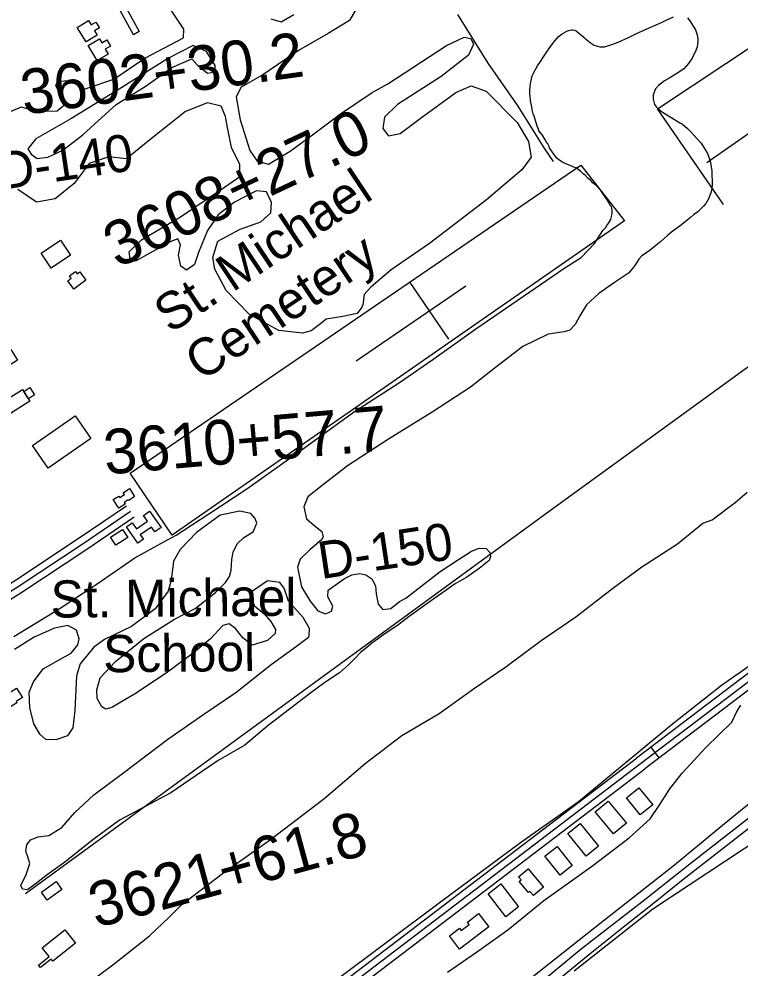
# Model space of a CAD drawing. Extents: x 3419139 to 3457078, y 540382 to 565875.
# Drawn here: x 3441162 to 3442772, y 548472 to 550592 of the extents above; entities that cross this region are included whole.
import ezdxf

# ---------------------------------------------------------------- set-up
doc = ezdxf.new("R2010")
doc.units = 0
for name, color, linetype in [('V-BLDG-IDEN', 7, 'Continuous'), ('V-BLDG-OTLN', 7, 'Continuous'), ('V-DTCH-CNTR', 7, 'Continuous'), ('V-RIVR-RANG-IDEN', 7, 'Continuous'), ('V-ROAD-CNTR', 7, 'Continuous'), ('V-SITE-OTLN', 7, 'Continuous'), ('V-SITE-OTLN-IDEN', 7, 'Continuous'), ('V-SITE-VEGE', 7, 'Continuous'), ('V-SURV-IDEN', 7, 'Continuous'), ('V-TOPO-SHOR', 7, 'Continuous')]:
    doc.layers.add(name, color=color, linetype=linetype)

msp = doc.modelspace()

# ---------------------------------------------------------------- linework, layer by layer
at = {"layer": 'V-BLDG-OTLN'}
for points in [[(3441393.1, 550631.6), (3441430.2, 550564.1), (3441417.2, 550556.9), (3441380.2, 550624.4)], [(3441312.2, 550540.8), (3441291.9, 550572.8), (3441317, 550588.6), (3441323.2, 550578.7), (3441333.3, 550585.1), (3441341.5, 550572), (3441330.7, 550565.2), (3441336.4, 550556.1)], [(3441336.6, 550499.1), (3441316.6, 550532.7), (3441341.4, 550547.5), (3441346.7, 550538.4), (3441358, 550545.1), (3441366, 550531.6), (3441354.1, 550524.5), (3441360.7, 550513.4)], [(3441254.4, 550098.4), (3441277.1, 550064.8), (3441233.9, 550035.7), (3441211.2, 550069.4)], [(3441311.3, 550008.9), (3441284.1, 549989.3), (3441270.7, 550007.8), (3441278.6, 550013.5), (3441274.9, 550018.6), (3441288.1, 550028.1), (3441291.7, 550023.2), (3441297.8, 550027.7)], [(3441185.7, 549738.9), (3441109.7, 549690.7), (3441085.1, 549729.7), (3441076.4, 549724.2), (3441060.2, 549749.6), (3441067.2, 549754), (3441043.7, 549791.1), (3441143.4, 549854.3), (3441158.5, 549830.4), (3441085.9, 549784.3), (3441118.6, 549732.7), (3441169.3, 549764.9)], [(3441185.8, 549769.5), (3441196.6, 549753.2), (3441183.1, 549744.1), (3441172.4, 549760.7)], [(3441322.6, 549655.6), (3441227.1, 549589.6), (3441192.1, 549640.2), (3441287.5, 549706)], [(3441408.5, 549543.7), (3441419.9, 549526.1), (3441406.8, 549517.5), (3441406, 549518.7), (3441396.5, 549512.5), (3441398.6, 549509.3), (3441384.8, 549500.3), (3441372.5, 549519.2), (3441384.8, 549527.3), (3441386.8, 549524.2), (3441397.1, 549530.8), (3441394.6, 549534.6)], [(3441453.5, 549493.4), (3441479, 549456.7), (3441465.5, 549447.4), (3441458, 549458.1), (3441432.8, 549440.6), (3441439.8, 549430.6), (3441427.4, 549422), (3441401.9, 549458.7), (3441414.7, 549467.6), (3441424.4, 549453.7), (3441449.1, 549470.8), (3441439.9, 549484)], [(3441404.6, 549434.5), (3441378.2, 549417.3), (3441366.5, 549435.2), (3441392.9, 549452.4)], [(3441122, 549076.8), (3441156.1, 549098.7), (3441169.6, 549077.6), (3441155.3, 549068.4), (3441157.1, 549065.7), (3441134.9, 549051.5), (3441122.9, 549070.3), (3441125.2, 549071.8)], [(3442549.3, 548815.4), (3442518.4, 548853.7), (3442546.1, 548876.1), (3442577, 548837.8)], [(3442489.2, 548772.9), (3442448.7, 548822.5), (3442477.9, 548846.3), (3442518.4, 548796.7)], [(3442428.8, 548723.4), (3442387.7, 548773.9), (3442415, 548796.2), (3442456.1, 548745.6)], [(3442370.1, 548681.1), (3442336.5, 548723.6), (3442363.4, 548744.9), (3442397.1, 548702.4)], [(3442298.8, 548695.3), (3442333.1, 548654.4), (3442310.5, 548635.5), (3442302.9, 548644.6), (3442299.9, 548642.1), (3442278.9, 548667.1), (3442283, 548670.6), (3442277.4, 548677.3)], [(3441257.6, 548649.2), (3441224.8, 548625.5), (3441212.2, 548643), (3441245, 548666.7)], [(3442249, 548588), (3442209.5, 548639.4), (3442238.1, 548661.4), (3442277.6, 548610)], [(3442210.8, 548566), (3442145.9, 548516), (3442123.2, 548545.5), (3442145.5, 548562.6), (3442149.3, 548557.6), (3442166.9, 548571.2), (3442163.3, 548575.9), (3442188.3, 548595.1)], [(3441288.3, 548529), (3441237.5, 548488.9), (3441233.6, 548493.8), (3441209.6, 548474.8), (3441205.3, 548480.3), (3441229.5, 548499.4), (3441213.9, 548519.1), (3441264.5, 548559.1)]]:
    msp.add_lwpolyline(points, close=True, dxfattribs=at)
at = {"layer": 'V-DTCH-CNTR'}
msp.add_lwpolyline([(3442141.4, 550601.8), (3442209, 550493.2), (3442276, 550397.3), (3442335.4, 550302.1), (3442354.4, 550273.9)], dxfattribs=at)
at = {"layer": 'V-ROAD-CNTR'}
msp.add_line((3442591.8, 548943), (3442573.6, 548966.9), dxfattribs=at)
for points in [[(3446783.6, 552186.4), (3446429.8, 551917.4), (3445909.7, 551525.7), (3445571.6, 551260.5), (3444950.1, 550786.4), (3444277, 550265.9), (3443810, 549903.5), (3443342.9, 549551.1), (3442540.9, 548942.1)], [(3442550, 548930.1), (3443352, 549539.1), (3443819.1, 549891.6), (3444286.2, 550254), (3444959.2, 550774.5), (3445580.8, 551248.6), (3445918.8, 551513.8), (3446438.8, 551905.4), (3446792.6, 552174.4)], [(3446801.7, 552162.5), (3446447.9, 551893.5), (3445928, 551502), (3445590, 551236.8), (3444968.3, 550762.6), (3444295.4, 550242.1), (3443828.2, 549879.7), (3443361, 549527.1), (3442559.1, 548918.2)], [(3441668.5, 547914.2), (3441772.2, 547996.7), (3441914, 548111.6), (3442044.3, 548215.4), (3442175.5, 548318.9), (3442292.2, 548412.8), (3442417.4, 548516.3), (3442555.8, 548623.7), (3442663.7, 548709.1), (3442788.6, 548806.9), (3442888.6, 548885.4), (3443031.6, 548992.2), (3443167.3, 549099.3), (3443278.3, 549183.2), (3443370.8, 549264.2), (3443455.1, 549334.3), (3443569.1, 549423.6), (3443685.2, 549512.4), (3443795.2, 549598.4), (3443909.2, 549686.9), (3444027.1, 549779.2), (3444132.9, 549864.1), (3444245, 549952.8), (3444348.5, 550027.2)], [(3440895.5, 549196), (3440937.8, 549215), (3440990, 549237.1), (3441040.8, 549267.2), (3441152, 549338.2), (3441296.5, 549433.6), (3441402.1, 549505.5)], [(3440901.6, 549182.3), (3440943.8, 549201.2), (3440996.8, 549223.7), (3441048.7, 549254.5), (3441160.1, 549325.6), (3441304.9, 549421.2), (3441410.6, 549493.1)], [(3440907.7, 549168.6), (3440949.8, 549187.5), (3441003.6, 549210.3), (3441056.5, 549241.7), (3441168.3, 549313), (3441313.2, 549408.7), (3441419, 549480.7)], [(3441562.5, 548197), (3442540.9, 548942.1)], [(3441571.6, 548185.1), (3442550, 548930.1)], [(3441580.6, 548173.1), (3442559.1, 548918.2)]]:
    msp.add_lwpolyline(points, dxfattribs=at)
at = {"layer": 'V-SITE-OTLN'}
for p, q in [((3441914.8, 549829.2), (3442159.9, 549996.2)), ((3442121.4, 549877.2), (3442035.1, 550003.8))]:
    msp.add_line(p, q, dxfattribs=at)
msp.add_lwpolyline([(3441409.8, 549578.6), (3442416.8, 550265.7), (3442513.9, 550141.5), (3441503.9, 549439.6)], close=True, dxfattribs=at)
at = {"layer": 'V-SITE-VEGE'}
for p, q in [((3442771.3, 549521.4), (3442788.1, 549535.7)), ((3442743.7, 549500.4), (3442760.5, 549512.4)), ((3442760.5, 549512.4), (3442771.3, 549521.4)), ((3442710.1, 549474.1), (3442721.7, 549482.7)), ((3442721.7, 549482.7), (3442731, 549489.5)), ((3442731, 549489.5), (3442743.7, 549500.4)), ((3442632.5, 549420.8), (3442689.3, 549466.6)), ((3442689.3, 549466.6), (3442710.1, 549474.1)), ((3442552.7, 549369.1), (3442632.5, 549420.8)), ((3442488, 549321.6), (3442552.7, 549369.1)), ((3442405.1, 549257.8), (3442488, 549321.6)), ((3442327.8, 549204.9), (3442405.1, 549257.8)), ((3442249.2, 549145.9), (3442327.8, 549204.9)), ((3442177.2, 549097.2), (3442249.2, 549145.9)), ((3442799.8, 549153), (3442730.7, 549104.3)), ((3442730.7, 549104.3), (3442621.3, 549018.3)), ((3442100.5, 549041.8), (3442177.2, 549097.2)), ((3442764.6, 549046.3), (3442773.9, 549060.5)), ((3442016.5, 548993.1), (3442100.5, 549041.8)), ((3442754.1, 549022.8), (3442764.6, 549046.3)), ((3442621.3, 549018.3), (3442410.2, 548843.7)), ((3442696, 548965.6), (3442754.1, 549022.8)), ((3441934.8, 548929.9), (3442016.5, 548993.1)), ((3442642.7, 548909), (3442696, 548965.6)), ((3441842.9, 548851.7), (3441934.8, 548929.9)), ((3442615.5, 548874), (3442642.7, 548909)), ((3442857.4, 548893.3), (3442737.2, 548795.3)), ((3442593.1, 548838.5), (3442615.5, 548874)), ((3441723.2, 548760.8), (3441842.9, 548851.7)), ((3442410.2, 548843.7), (3442282.1, 548753.5)), ((3442571.3, 548807.1), (3442593.1, 548838.5)), ((3442524.1, 548764.4), (3442571.3, 548807.1)), ((3442577.5, 548606.2), (3442879.7, 548805.9)), ((3442737.2, 548795.3), (3442625.4, 548703.2)), ((3441616.2, 548685), (3441723.2, 548760.8)), ((3442440.1, 548700.6), (3442524.1, 548764.4)), ((3442282.1, 548753.5), (3442100.1, 548618.7)), ((3442333.7, 548624.2), (3442440.1, 548700.6)), ((3442625.4, 548703.2), (3442448.8, 548564.2)), ((3441525.5, 548615.2), (3441616.2, 548685)), ((3441497.1, 548587.6), (3441525.5, 548615.2)), ((3442100.1, 548618.7), (3441866.1, 548443.6)), ((3442253.2, 548559.2), (3442333.7, 548624.2)), ((3442401.5, 548467.7), (3442577.5, 548606.2)), ((3441453.5, 548545.4), (3441497.1, 548587.6)), ((3442183.7, 548509.3), (3442253.2, 548559.2)), ((3442448.8, 548564.2), (3442287.4, 548436.6)), ((3441371.3, 548481), (3441453.5, 548545.4)), ((3442118.4, 548464.8), (3442183.7, 548509.3)), ((3441268.5, 548405.2), (3441371.3, 548481))]:
    msp.add_line(p, q, dxfattribs=at)
for points in [[(3441121, 550376.5), (3441167.8, 550395.8), (3441198.1, 550386), (3441247.3, 550387.1), (3441264.4, 550401), (3441254.1, 550424.1), (3441243.8, 550443), (3441248.1, 550453.3), (3441277.9, 550454.4), (3441307.6, 550435.5), (3441373.8, 550457.9), (3441443.2, 550504.5), (3441529.5, 550549.8), (3441529.6, 550569.2), (3441496.9, 550618.5), (3441453.3, 550676.3), (3441421.2, 550734.1), (3441398.9, 550777.9), (3441395.9, 550808.8)], [(3441916.5, 550616.9), (3441900.1, 550588.4), (3441852.6, 550559.4), (3441785.7, 550521.3), (3441706.7, 550467.4), (3441658, 550439.6), (3441647, 550418.3), (3441656, 550366.7), (3441677.7, 550298.6), (3441693.5, 550274.9), (3441719, 550268.2), (3441767.6, 550297.2), (3441820.5, 550336), (3441879.5, 550380.2), (3441950.7, 550428), (3441985.4, 550447.3)], [(3441724.6, 550592.5), (3441747.6, 550585.7), (3441775.6, 550602.1)], [(3442323, 550342.4), (3442321.7, 550346.4), (3442319.1, 550352.5), (3442317.3, 550358.2), (3442312.6, 550374.8), (3442310.4, 550380.4), (3442308.2, 550389.2), (3442306.9, 550395.7), (3442305.2, 550405.3), (3442303.9, 550410.6), (3442303.5, 550419.7), (3442302.6, 550425.4), (3442302.7, 550431.5), (3442303.6, 550442.8), (3442304.5, 550451.6), (3442307.5, 550465.1), (3442311.5, 550472.9), (3442319.4, 550487.3), (3442326.4, 550496.9), (3442332.9, 550507.3), (3442344.8, 550525.2), (3442353.5, 550536.5), (3442365.8, 550551.8), (3442374.5, 550558.7), (3442385, 550564.8), (3442389.4, 550566.5), (3442395.5, 550567.8), (3442398.5, 550567.8), (3442402.9, 550566.9), (3442405.9, 550565.2), (3442411.6, 550560.8), (3442415.1, 550557.8), (3442423.4, 550551.2), (3442426.4, 550548.1), (3442437.3, 550539.4), (3442446, 550533.7), (3442459.1, 550530.2), (3442469.1, 550530.1), (3442486.1, 550534.9), (3442499.7, 550540.5), (3442523.3, 550551), (3442539.4, 550558.8), (3442562.6, 550569.2), (3442596.6, 550583.9), (3442608.4, 550590), (3442623.3, 550597)], [(3442654.7, 550594.3), (3442660.3, 550587.7), (3442667.7, 550575.9), (3442672.5, 550567.6), (3442675.5, 550558.5), (3442676.8, 550553.7), (3442677.7, 550545.4), (3442677.7, 550540.1), (3442676.3, 550529.7), (3442673.3, 550521.4), (3442664.9, 550504.8), (3442657.1, 550492.6), (3442646.6, 550480.9)], [(3441985.4, 550447.3), (3442116.8, 550532.6), (3442155.7, 550551.4), (3442170.9, 550548.3), (3442176.9, 550535.5), (3442165.9, 550511.3), (3442104.5, 550463.4), (3442007.1, 550401.1), (3441977.9, 550372.6), (3441974.2, 550347.7), (3441986.9, 550331.3), (3442013.1, 550336.7), (3442057.5, 550370), (3442137.2, 550428.1), (3442171.8, 550442.6), (3442205.2, 550431), (3442274.3, 550361), (3442299.7, 550318.4), (3442305.7, 550283.8), (3442285, 550255.3), (3442205.8, 550188.7), (3442078.7, 550091.2), (3441992.9, 550031.9), (3441947.9, 549993.1), (3441932.7, 549976.8), (3441929.6, 549954.3), (3441927.7, 549948.8), (3441916.8, 549934.9), (3441885.2, 549928.3), (3441847.5, 549922.3), (3441835.3, 549911.4), (3441814, 549896.3), (3441794.6, 549890.8), (3441741.8, 549896.4), (3441676.3, 549932.4), (3441624.8, 549986), (3441599.4, 550033.4), (3441594.6, 550059.5), (3441606.2, 550095.9), (3441655.5, 550122.6), (3441701.6, 550139.5), (3441724.2, 550159.4), (3441725.4, 550182.5), (3441714.6, 550206.2), (3441692.1, 550208.1), (3441642.8, 550183.3), (3441606.9, 550154.9), (3441582.6, 550119.7), (3441563, 550070.5), (3441553.8, 550043.8), (3441536.2, 550031.7), (3441522.9, 550040.3), (3441518.1, 550064.6), (3441522.4, 550087.6), (3441516.9, 550101), (3441501.1, 550095.6), (3441453.7, 550069.6), (3441422.1, 550051.4), (3441409.9, 550056.9), (3441408.2, 550072.1), (3441435.5, 550098.8), (3441522.5, 550150.2), (3441621.1, 550216.8), (3441655.1, 550240.4), (3441655.2, 550267.1), (3441636.4, 550305.4), (3441627.4, 550349.8), (3441623.2, 550374.7), (3441613.6, 550397.2), (3441582.6, 550404.5), (3441534, 550385.8), (3441450.6, 550319.2), (3441402, 550279.8), (3441362.5, 550284.2), (3441318.7, 550269.7), (3441285.2, 550224.8), (3441242.6, 550190.3), (3441201.3, 550183.1), (3441158.9, 550211.2)], [(3442646.6, 550480.9), (3442634.8, 550472.2), (3442615.5, 550460.4), (3442603.3, 550453.9), (3442589.8, 550443.9), (3442583.6, 550436.1), (3442577.9, 550422.6), (3442577.9, 550413), (3442581.4, 550401.2), (3442585.3, 550395.1), (3442594.4, 550387.2), (3442602.3, 550381.5), (3442616.2, 550373.6), (3442639.3, 550359.2), (3442643.2, 550357), (3442655, 550347.3), (3442663.2, 550339.5), (3442676.3, 550324.2), (3442685, 550314.6), (3442691.5, 550304.9), (3442698.5, 550293.6), (3442701.5, 550285.7), (3442705.4, 550274.8), (3442707.1, 550266.5), (3442708.9, 550253.4), (3442709.3, 550244.3), (3442710.1, 550229.4), (3442710.1, 550219.8), (3442707.4, 550206.3), (3442704.4, 550198), (3442701.3, 550190.6), (3442695.6, 550180.2), (3442690.8, 550174.5), (3442683.3, 550166.7), (3442677.7, 550161.9), (3442668, 550154.5), (3442661.1, 550148.8), (3442650.1, 550139.7), (3442641.4, 550132.7), (3442628.3, 550123.2), (3442619.1, 550116.2), (3442609.9, 550108.8), (3442595.1, 550095.3), (3442583.7, 550086.2), (3442571.4, 550076.2), (3442551.8, 550062.7), (3442545.8, 550056), (3442538.6, 550044), (3442531.8, 550035.2), (3442523.2, 550024.6), (3442491.4, 550003.9), (3442457, 549979.2), (3442429.5, 549953.7), (3442414.6, 549929.2), (3442403.7, 549910), (3442391.9, 549897.6), (3442379.5, 549893.4), (3442343.6, 549888.7), (3442287.1, 549860.8), (3442226.1, 549814.4), (3442170.1, 549770.2), (3442084.6, 549714.3), (3441986.7, 549653.9), (3441895.2, 549594.3), (3441838.6, 549551), (3441807.2, 549525.1), (3441797.8, 549503.4), (3441803.8, 549476.6), (3441823.9, 549459.3), (3441838.4, 549448.4), (3441841.1, 549436.3), (3441837.4, 549429.4), (3441812.3, 549407.7), (3441789.7, 549386.1), (3441783.9, 549368.6), (3441792.8, 549324.8), (3441812.4, 549292.5), (3441828.9, 549271.3), (3441846.4, 549264.3), (3441860, 549270.3), (3441862.4, 549281.5), (3441851.6, 549302), (3441852.3, 549316.8), (3441889.1, 549343.3), (3441904.8, 549351.1), (3441922.7, 549354.4), (3441936.5, 549351.6), (3441949.8, 549342.5), (3441957.9, 549326.5), (3441959.7, 549308.7), (3441964.1, 549286.1), (3441974.4, 549274.3), (3441992.2, 549276.4), (3442011.5, 549292), (3442026, 549299.2), (3442102.5, 549358.5), (3442143.6, 549385.2), (3442172, 549404.2), (3442189.5, 549410.5), (3442204.9, 549410.1), (3442213.3, 549401.4)], [(3441150.2, 549213.8), (3441251.7, 549275.4), (3441334.2, 549330.1), (3441420.6, 549389.3), (3441485.6, 549424.8), (3441512.8, 549439.8), (3441583.8, 549486.1), (3441670.5, 549543.6), (3441791.7, 549629.3), (3441911.1, 549715.6), (3442009.6, 549779), (3442085.8, 549832.3), (3442182.2, 549900.2), (3442288.6, 549973), (3442381.1, 550036.4), (3442417.6, 550059.3), (3442446.9, 550091.2), (3442466, 550119.6), (3442471.7, 550125.7), (3442474.7, 550131.4), (3442478.7, 550137), (3442483.5, 550144.4), (3442485.2, 550150.6), (3442486.6, 550159.7), (3442486.6, 550165.4), (3442484.9, 550172.8), (3442482.2, 550175.9), (3442478.8, 550182.4), (3442475.3, 550188.1), (3442461.4, 550209.1), (3442450.5, 550220.4), (3442443.5, 550226.6), (3442437.9, 550232.2), (3442433.1, 550236.2), (3442426.1, 550243.2), (3442421.8, 550246.2), (3442416.5, 550251.9), (3442406.1, 550259.4), (3442400.9, 550261.1), (3442393, 550265.1), (3442383, 550269), (3442378.6, 550271.2), (3442373.8, 550273.4), (3442370.8, 550275.6), (3442367.3, 550277.8), (3442363, 550281.7), (3442354.7, 550292.6), (3442349.9, 550299.6), (3442346.9, 550304.4), (3442345.6, 550307.5), (3442344.3, 550310.1), (3442342.5, 550313.2), (3442340.8, 550314.9), (3442339.5, 550316.7), (3442336.4, 550324.1), (3442330.8, 550332.4), (3442323, 550342.4)], [(3442213.3, 549401.4), (3442214.8, 549392.6), (3442211.5, 549383.6), (3442189.7, 549365.2), (3442161.9, 549346), (3442136.2, 549331.2), (3442082.7, 549294), (3442033.2, 549258.5), (3442007.2, 549238.3), (3441979.1, 549219.4), (3441964.6, 549209.4), (3441949.8, 549198.9), (3441938.3, 549189.3), (3441924.7, 549177.9), (3441913.2, 549165.8), (3441898, 549150.2), (3441877.5, 549132.7), (3441844.5, 549111.1), (3441810.4, 549085.5), (3441766, 549051.2), (3441718.5, 549015.4), (3441666.2, 548971.2), (3441606.7, 548936.6), (3441557.7, 548903.5), (3441500.6, 548864.4), (3441386.1, 548803.4), (3441327.1, 548759.8), (3441264.3, 548710.2), (3441224.4, 548681.9), (3441198.1, 548660.6), (3441180.5, 548647.9), (3441169.4, 548649.8), (3441165.8, 548657.9), (3441177.9, 548682.3), (3441186.4, 548706.8), (3441181.6, 548722.2), (3441177.1, 548734.8), (3441179, 548749), (3441187.4, 548759.6), (3441204.4, 548766.8), (3441228.2, 548769.7), (3441257.2, 548787.2), (3441286.3, 548821.2), (3441328.6, 548860.3), (3441396.3, 548910.2), (3441494.5, 548984.8), (3441574.3, 549040.5), (3441645.9, 549088.9), (3441725.1, 549151.5), (3441781.4, 549192.4), (3441808, 549212.5), (3441809.5, 549215.5), (3441810.7, 549231.2), (3441796.6, 549256.3), (3441763.5, 549292.6), (3441753.9, 549321.3), (3441744.3, 549334), (3441716.5, 549338.3), (3441683.3, 549314.8), (3441679.9, 549301.2), (3441687.7, 549282.2), (3441709.4, 549264.1), (3441724.5, 549247.4), (3441734.4, 549229), (3441733.8, 549220.5), (3441716.8, 549204.9), (3441682.7, 549194.4), (3441661.9, 549211.1), (3441645.7, 549231.9), (3441631.5, 549242.2), (3441616.7, 549238), (3441589.2, 549208.2), (3441547.5, 549174.5), (3441493.7, 549134.2), (3441423.6, 549087), (3441369.5, 549055.1), (3441355.6, 549051.2), (3441346.5, 549056.7), (3441336.3, 549075.1), (3441335.5, 549094.4), (3441342.8, 549121.6), (3441377, 549158), (3441440.7, 549209.2), (3441509, 549252.1), (3441555.3, 549275.9), (3441600.6, 549311.7), (3441623.3, 549334.6), (3441632.1, 549347.8), (3441635.7, 549362), (3441637.3, 549385.5), (3441640.3, 549401.8), (3441649.1, 549420.8), (3441664, 549434.9), (3441685.1, 549447.6), (3441693.3, 549466.3), (3441689.1, 549477.4), (3441679.5, 549488.6), (3441655.3, 549493.2), (3441611.3, 549484.6), (3441558.4, 549446.1), (3441521.8, 549407.8)], [(3441521.8, 549407.8), (3441507.2, 549381.9), (3441501.7, 549339.1), (3441494.7, 549315.2), (3441465.9, 549275.5), (3441413.3, 549235.8), (3441352.6, 549206.7), (3441328.8, 549189.8), (3441298.5, 549152.5), (3441290.6, 549126.2), (3441286.5, 549048.4), (3441281.9, 549010.1), (3441270.1, 548992), (3441243.8, 548982.7), (3441222.1, 548983.7), (3441208.8, 548994.9), (3441195.3, 549019), (3441186.3, 549055.3), (3441184.9, 549089.7), (3441194.6, 549112.6), (3441216.1, 549141.2), (3441249.9, 549161), (3441278, 549176.7), (3441293.5, 549195.3), (3441296.5, 549208.3), (3441290.2, 549227.6), (3441270.6, 549238.2), (3441241.3, 549232), (3441195.7, 549212.1), (3441151.9, 549184.5)]]:
    msp.add_lwpolyline(points, dxfattribs=at)
msp.add_lwpolyline([(3441188.8, 550290.1), (3441202.1, 550280.3), (3441226.4, 550283.9), (3441259.9, 550299), (3441304.3, 550333.5), (3441338.4, 550365), (3441379.2, 550400.8), (3441446.1, 550442.5), (3441503.2, 550483.7), (3441547.6, 550503), (3441559.7, 550489.6), (3441582.8, 550470.7), (3441599.2, 550473.7), (3441599.8, 550488.3), (3441580.5, 550519.3), (3441550.7, 550532.7), (3441496, 550504.9), (3441385.3, 550435.4), (3441277.7, 550368.8), (3441199.2, 550324.6), (3441181.5, 550302.2)], close=True, dxfattribs=at)
at = {"layer": 'V-TOPO-SHOR'}
for points in [[(3442697.9, 550271.7), (3444081.1, 551237.4), (3444845.4, 551772.8)], [(3445259.7, 551584.9), (3444468.3, 551033.4), (3442348.7, 549495.1), (3441176.2, 548639.4)], [(3442734.8, 550178), (3442587.9, 550391.2), (3443045.5, 550695.7)], [(3442363.2, 548445.5), (3442437.3, 548505.9), (3442512, 548565.5), (3442582.4, 548621.5), (3442644.1, 548671.1), (3442704.5, 548718.4), (3442802.2, 548793.9)]]:
    msp.add_lwpolyline(points, dxfattribs=at)

# ---------------------------------------------------------------- texts
at = {"layer": 'V-BLDG-IDEN'}
for s, p in [('St. Michael', (3441232.7, 549255.7)), ('School', (3441350.1, 549133.7))]:
    msp.add_text(s, height=83, rotation=0.4743, dxfattribs=at).set_placement(p)
at = {"layer": 'V-RIVR-RANG-IDEN'}
for s, rotation, p in [('D-140', 8.4613, (3441122, 550210.5)), ('D-150', 8.6273, (3441836.4, 549341.7))]:
    msp.add_text(s, height=83, rotation=rotation, dxfattribs=at).set_placement(p)
at = {"layer": 'V-SITE-OTLN-IDEN'}
for s, p in [('St. Michael', (3441500, 549888.5)), ('Cemetery', (3441569.4, 549781.9))]:
    msp.add_text(s, height=83, rotation=33.6793, dxfattribs=at).set_placement(p)
at = {"layer": 'V-SURV-IDEN'}
for s, rotation, p in [('3602+30.2', 7.8547, (3441172.7, 550377.8)), ('3608+27.0', 25.1839, (3441381.6, 550034.8)), ('3610+57.7', 4.9628, (3441355, 549575)), ('3621+61.8', 15.2296, (3441334, 548562.6))]:
    msp.add_text(s, height=100, rotation=rotation, dxfattribs=at).set_placement(p)

doc.saveas('drawing.dxf')
